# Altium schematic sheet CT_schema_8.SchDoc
size 278 x 170 mm
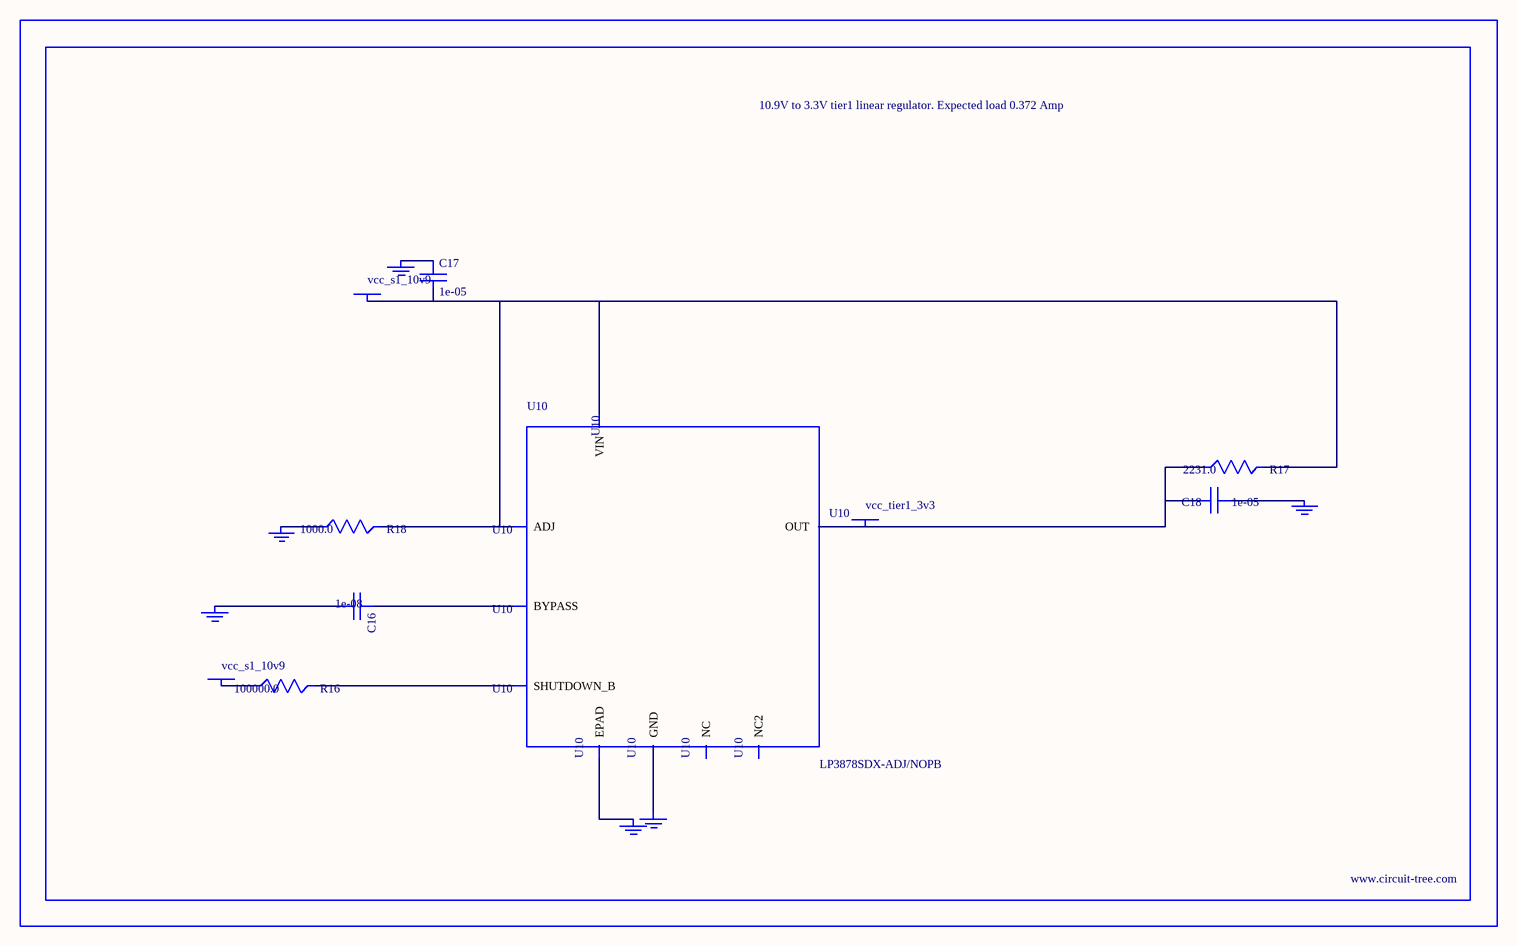
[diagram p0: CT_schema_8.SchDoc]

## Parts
BORDER7  (no value)
C16  1e-08  [C0402]
C17  1e-05  [C1206]
C18  1e-05  [C1210]
GND_INSTANCE_7_0  (no value)
GND_INSTANCE_7_1  (no value)
GND_INSTANCE_7_2  (no value)
GND_INSTANCE_7_3  (no value)
GND_INSTANCE_7_4  (no value)
GND_INSTANCE_7_5  (no value)
POWER_INSTANCE_7_0  vcc_s1_10v9
POWER_INSTANCE_7_1  vcc_s1_10v9
POWER_INSTANCE_7_2  vcc_tier1_3v3
R16  100000.0  [R0603]
R17  2231.0  [R0603]
R18  1000.0  [R0603]
U10  LP3878SDX-ADJ/NOPB  [WSON-8]

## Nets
NetC16_1: C16.1 U10.1(BYPASS)
NetC16_2: C16.2 GND_INSTANCE_7_0.0(GND)
NetC17_1: C17.1 GND_INSTANCE_7_1.0(GND)
NetC17_2: C17.2 POWER_INSTANCE_7_0.0(PWR) R17.2 R18.2 U10.4(VIN) U10.6(ADJ)
NetC18_1: C18.1 GND_INSTANCE_7_2.0(GND)
NetC18_2: C18.2 POWER_INSTANCE_7_2.0(PWR) R17.1 U10.5(OUT)
NetGND_INSTANCE_7_3_0: GND_INSTANCE_7_3.0(GND) R18.1
NetGND_INSTANCE_7_4_0: GND_INSTANCE_7_4.0(GND) U10.PAD(EPAD)
NetGND_INSTANCE_7_5_0: GND_INSTANCE_7_5.0(GND) U10.3(GND)
NetPOWER_INSTANCE_7_1_0: POWER_INSTANCE_7_1.0(PWR) R16.1
NetR16_2: R16.2 U10.8(SHUTDOWN_B)

Not connected (* = marked no-connect by the designer): U10 2(NC) 7(NC2)

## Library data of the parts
BORDER7 = BORDER_PAGE7
C16 = C0402C103K3RAC
C17 = C1206C106K3RACTU
C18 = GRM32DR61E106MA12L
GND_INSTANCE_7_0-GND_INSTANCE_7_5 = GND
POWER_INSTANCE_7_0-POWER_INSTANCE_7_2 = PWR
R16 = RC0603JR-07100KL
R17 = R17
R18 = RC0603JR-071KL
